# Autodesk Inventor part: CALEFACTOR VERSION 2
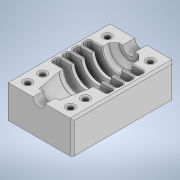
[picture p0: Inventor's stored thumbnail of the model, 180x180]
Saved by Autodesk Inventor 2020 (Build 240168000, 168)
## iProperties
Created: 2022-10
Part Number: CALEFACTOR VERSION 2
Material: Genérico
Document SubType Name: Modeling
Designer: SEBAS
Density: 1 g/cm^3
Appearance: Valor por defecto
Author: SEBAS
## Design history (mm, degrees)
sketch "Boceto1"
  geometry: L1 (0, 0)-(0, 102); L2 (0, 102)-(33, 102); L3 (0, 0)-(33, 0); L4 (33, 0)-(33, 12); L5 (33, 12)-(23, 12); L6 (18, 17)-(18, 24); L7 (18, 67)-(18, 62); L8 (18, 17)-(23, 12); L9 (18, 24)-(5, 24); L10 (5, 24)-(5, 31.25); L11 (5, 31.25)-(18, 31.25); L12 (18, 31.25)-(18, 34.25); L13 (18, 34.25)-(5, 34.25); L14 (5, 34.25)-(5, 41.5); L15 (5, 41.5)-(18, 41.5); L16 (18, 41.5)-(18, 44.5); L17 (18, 44.5)-(5, 44.5); L18 (5, 44.5)-(5, 51.75); L19 (5, 51.75)-(18, 51.75); L20 (18, 62)-(5, 62); L21 (5, 62)-(5, 54.75); L22 (5, 54.75)-(18, 54.75); L23 (18, 54.75)-(18, 51.75); L24 (18, 67)-(23, 92); L25 (33, 102)-(33, 92); L26 (33, 92)-(23, 92); L27 (18, 17)-(18, 7.5); L28 (33, 102)-(33, 0)
  constraints: 57 end point, 12 perpendicular, 6 horizontal alignment, 6 vertical, 6 vertical alignment, 5 collinear, 5 horizontal, 5 point on line
  dimensions: "d0" = 102 distance of L1.start L1.end; "d1" = 33 distance of L1.end L2.end; "d6" = 5 distance of L7.start L7.end; "d7" = 7 distance of L6.start L6.end; "d12" = 3 distance of L11.end L12.end; "d14" = 13 distance of L7.end L20.end; "d15" = 25 vertical distance of L7.start L24.end; "d16" = 5 horizontal distance of L7.start L24.end; "d17" = 45 deg angle of L27 L8; "d18" = 38 distance of L9.end L20.end; "d20" = 10 distance of L2.end L25.end; "d21" = 5 distance between parallel lines of L1 L21
revolve "Revolución1" sketch "Boceto1" stored, may be unused: angle "d22" = 180 deg
sketch "Boceto2"
  geometry: L1 (-33, -33)-(33, -33); L2 (-33, -33)-(-33, 0); L3 (-33, 0)-(33, 0); L4 (33, 0)-(33, -33); A1 r 33 centre (0, 0) between (-33, 0) and (33, 0) reference; 2 further points
  constraints: 8 end point, 2 perpendicular, 1 horizontal, 1 midpoint, 1 point on circle, 1 tangent, 1 vertical, 1 vertical alignment
extrude "Extrusión1" join sketch "Boceto2" stored distance "d23" = 10; taper "d24" = 0 deg
sketch "Boceto3"
  geometry: L1 (23, 33)-(43, 33) reference; C1 r 6 at (33, 33); 1 further point
  constraints: 1 centre point, 1 midpoint
  dimensions: "d25" = 12 diameter of C1
extrude "Extrusión2" cut sketch "Boceto3" stored distance "d26" = 10; taper "d27" = 0 deg
fillet "Empalme2" dims "d29" = 2
fillet "Empalme3" dims "d33" = 1
sketch "Boceto4"
  geometry: L1 (-15.5, 90)-(27.5, 90); C1 r 2.5 at (-15.5, 90); C2 r 2.5 at (27.5, 90); C3 r 2.5 at (-15.5, 10); C4 r 2.5 at (27.5, 10); C5 r 2.5 at (-15.5, 25); C6 r 2.5 at (27.5, 25); 2 further points
  constraints: 6 centre point, 5 equal radius, 5 vertical alignment, 2 end point, 2 horizontal alignment, 1 horizontal, 1 midpoint
  dimensions: "d34" = 43 distance of L1.start L1.end; "d35" = 5 diameter of C2; "d36" = 12 distance of point (6, 102) point (6, 90); "d37" = 77 vertical distance of C6.centre point (6, 102); "d38" = 15 distance of C4.centre C6.centre
extrude "Extrusión3" cut sketch "Boceto4" distance "d39" = 15; taper "d40" = 0 deg
fillet "Empalme4" dims "d41" = 2
chamfer "Chaflán2" distance "d42" = 2; stored, may be unused: second distance "d43" = 2, angle "d44" = 45 deg
node "Sólido1"
